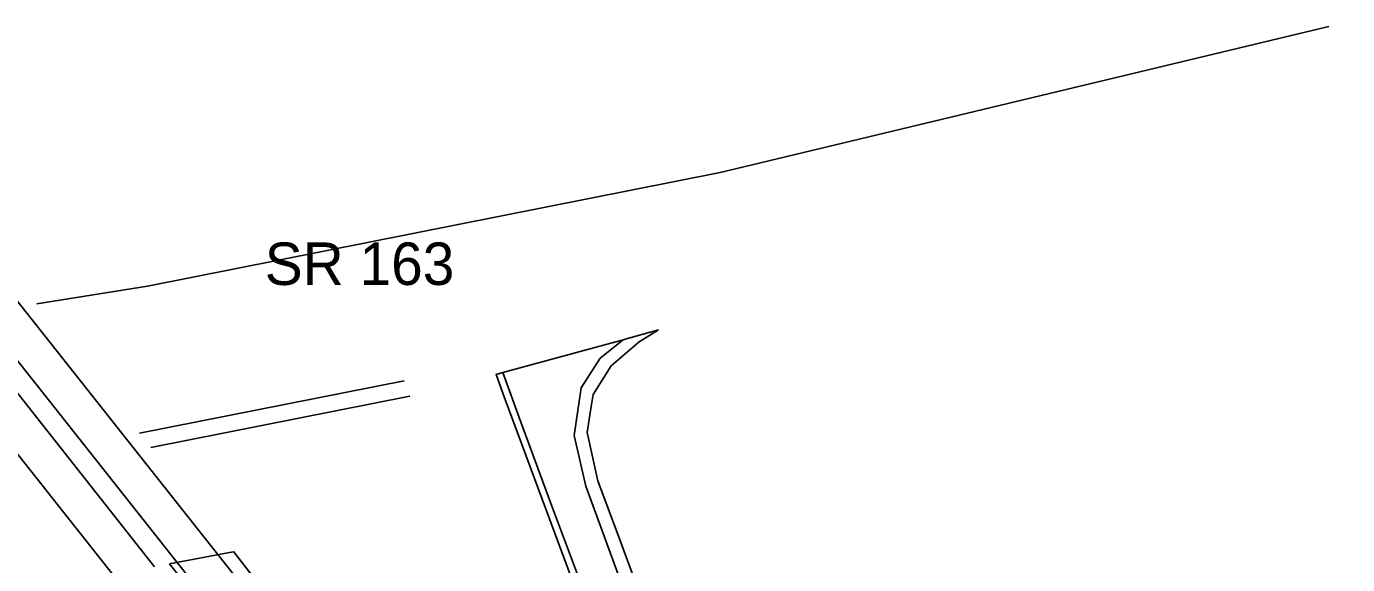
# Model space of a CAD drawing. Extents: x 1855721 to 1876784, y 662259 to 674089.
# Drawn here: x 1856655 to 1857215, y 673659 to 673887 of the extents above; entities that cross this region are included whole.
import ezdxf

# ---------------------------------------------------------------- set-up
doc = ezdxf.new("R2010")
doc.units = 0
for name, color, linetype in [('_CIVIL_CONSTRUCTION', 7, 'Continuous'), ('GE_X_Alignment_100_Curve_Data', 7, 'Continuous'), ('PV_X_EOP', 7, 'Continuous'), ('PV_X_Shoulder', 7, 'Continuous'), ('SC_Scratch1', 7, 'Continuous')]:
    doc.layers.add(name, color=color, linetype=linetype)

msp = doc.modelspace()

# ---------------------------------------------------------------- linework, layer by layer
at = {"layer": '_CIVIL_CONSTRUCTION'}
for p, q in [((1856857, 673740.67), (1856907.94, 673754.45)), ((1856715.89, 673659.59), (1856742.94, 673664.73))]:
    msp.add_line(p, q, dxfattribs=at)
for points in [[(1856907.94, 673754.45), (1856898.32, 673746.66), (1856890.16, 673734.18), (1856887.31, 673714.01), (1856892.25, 673692.55), (1856907.26, 673651.21), (1856926.05, 673599.53), (1856939.44, 673563.9), (1856970.18, 673481.83), (1856997.54, 673409.99), (1857010.24, 673378.46), (1857019.53, 673358.08), (1857042.16, 673313.09), (1857061.25, 673280.57), (1857083.54, 673246.08), (1857095.78, 673228.1), (1857114.49, 673202.22)], [(1856736.42, 673663.49), (1856773.03, 673617.2), (1856819.3, 673558.86), (1856858.11, 673510.2), (1856909.33, 673445.54), (1856977.66, 673360.11)]]:
    msp.add_lwpolyline(points, dxfattribs=at)
at = {"layer": 'GE_X_Alignment_100_Curve_Data'}
for p, q in [((1856736.42, 673663.49), (1856616.28, 673815.4)), ((1856709.64, 673658.36), (1856589.82, 673810.1)), ((1856599.62, 673811.34), (1856719.16, 673660.21)), ((1856572.39, 673806.34), (1856692.3, 673654.54))]:
    msp.add_line(p, q, dxfattribs=at)
for points in [[(1856995.1, 673370.58), (1856979.23, 673412.62), (1856964.76, 673451.11), (1856947.16, 673498.42), (1856931.99, 673539.09), (1856917.81, 673577.08), (1856895.42, 673636.94), (1856877.21, 673685.56), (1856864.56, 673720.05), (1856857, 673740.67)], [(1857084.52, 673199.44), (1857058.84, 673231.89), (1857036.21, 673260.51), (1857005.72, 673299.13), (1856977.91, 673334.27), (1856956.33, 673361.4), (1856932.27, 673391.54), (1856905.5, 673425.34), (1856874.29, 673464.62), (1856845.61, 673500.69), (1856797.58, 673561.38), (1856776.76, 673587.64), (1856740.03, 673633.92), (1856719.16, 673660.21)]]:
    msp.add_lwpolyline(points, dxfattribs=at)
at = {"layer": 'PV_X_EOP'}
msp.add_line((1856703.3, 673714.94), (1856815.24, 673737.14), dxfattribs=at)
msp.add_lwpolyline([(1856659.72, 673769.8), (1856706.61, 673777.23), (1856949.12, 673825.38), (1857206.7, 673887.27)], dxfattribs=at)
at = {"layer": 'PV_X_Shoulder'}
msp.add_line((1856708.07, 673708.91), (1856817.71, 673730.66), dxfattribs=at)
at = {"layer": 'SC_Scratch1'}
msp.add_line((1856922.95, 673758.75), (1856907.82, 673754.42), dxfattribs=at)
for points in [[(1857125.9, 673192.38), (1857106.85, 673217.86), (1857089.03, 673243.2), (1857071.28, 673270.35), (1857059.35, 673290.79), (1857046.95, 673312.63), (1857038.08, 673330.2), (1857027.78, 673351.06), (1857018.79, 673372.97), (1857010.27, 673394.49), (1856997.68, 673427.1), (1856985.51, 673459.37), (1856969.73, 673501.38), (1856952.87, 673546.06), (1856924.71, 673620.84), (1856906.01, 673671.37), (1856897.33, 673694.81), (1856892.8, 673715.23), (1856894.39, 673726.2), (1856895.28, 673731.39), (1856902.96, 673743.51), (1856914.8, 673753.61), (1856922.95, 673758.75)], [(1856857, 673740.67), (1856854.2, 673739.81), (1856857.68, 673730.29), (1856911.85, 673584.37), (1856944.24, 673498.28), (1856968.35, 673433.32), (1856983.48, 673393.51), (1856988.89, 673379.15), (1856992.64, 673369.1)], [(1856982.43, 673362.97), (1856941.59, 673413.15), (1856903.88, 673460.69), (1856867.68, 673506.36), (1856828.81, 673555.19), (1856798.76, 673593), (1856770.3, 673629.04), (1856752.46, 673651.62), (1856752.81, 673652.27), (1856743.08, 673664.76)], [(1857506.27, 672661.92), (1857419.93, 672771.16), (1857315.59, 672902.87), (1857226.39, 673015.29), (1857156.27, 673103.7), (1857102.52, 673171.6), (1857037.75, 673253.29), (1856965.28, 673344.85), (1856882.51, 673448.91), (1856802.82, 673549.45), (1856753.58, 673611.84), (1856715.89, 673659.59)]]:
    msp.add_lwpolyline(points, dxfattribs=at)

# ---------------------------------------------------------------- texts
msp.add_text('SR 163', height=18, dxfattribs=at).set_placement((1856756.25, 673777.73))

doc.saveas('drawing.dxf')
